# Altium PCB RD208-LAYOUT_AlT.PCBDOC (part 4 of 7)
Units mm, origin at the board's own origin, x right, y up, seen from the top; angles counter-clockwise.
Board outline 240 x 150 mm, 6 copper layers (TOP, Mid-Layer 1, Mid-Layer 2, Mid-Layer 3, Mid-Layer 4, BOTTOM), stack 1.422 mm thick; 773 components, 409 nets, 3936 pads, 97 vias.
Unrouted connection lines stored in the file: 1.
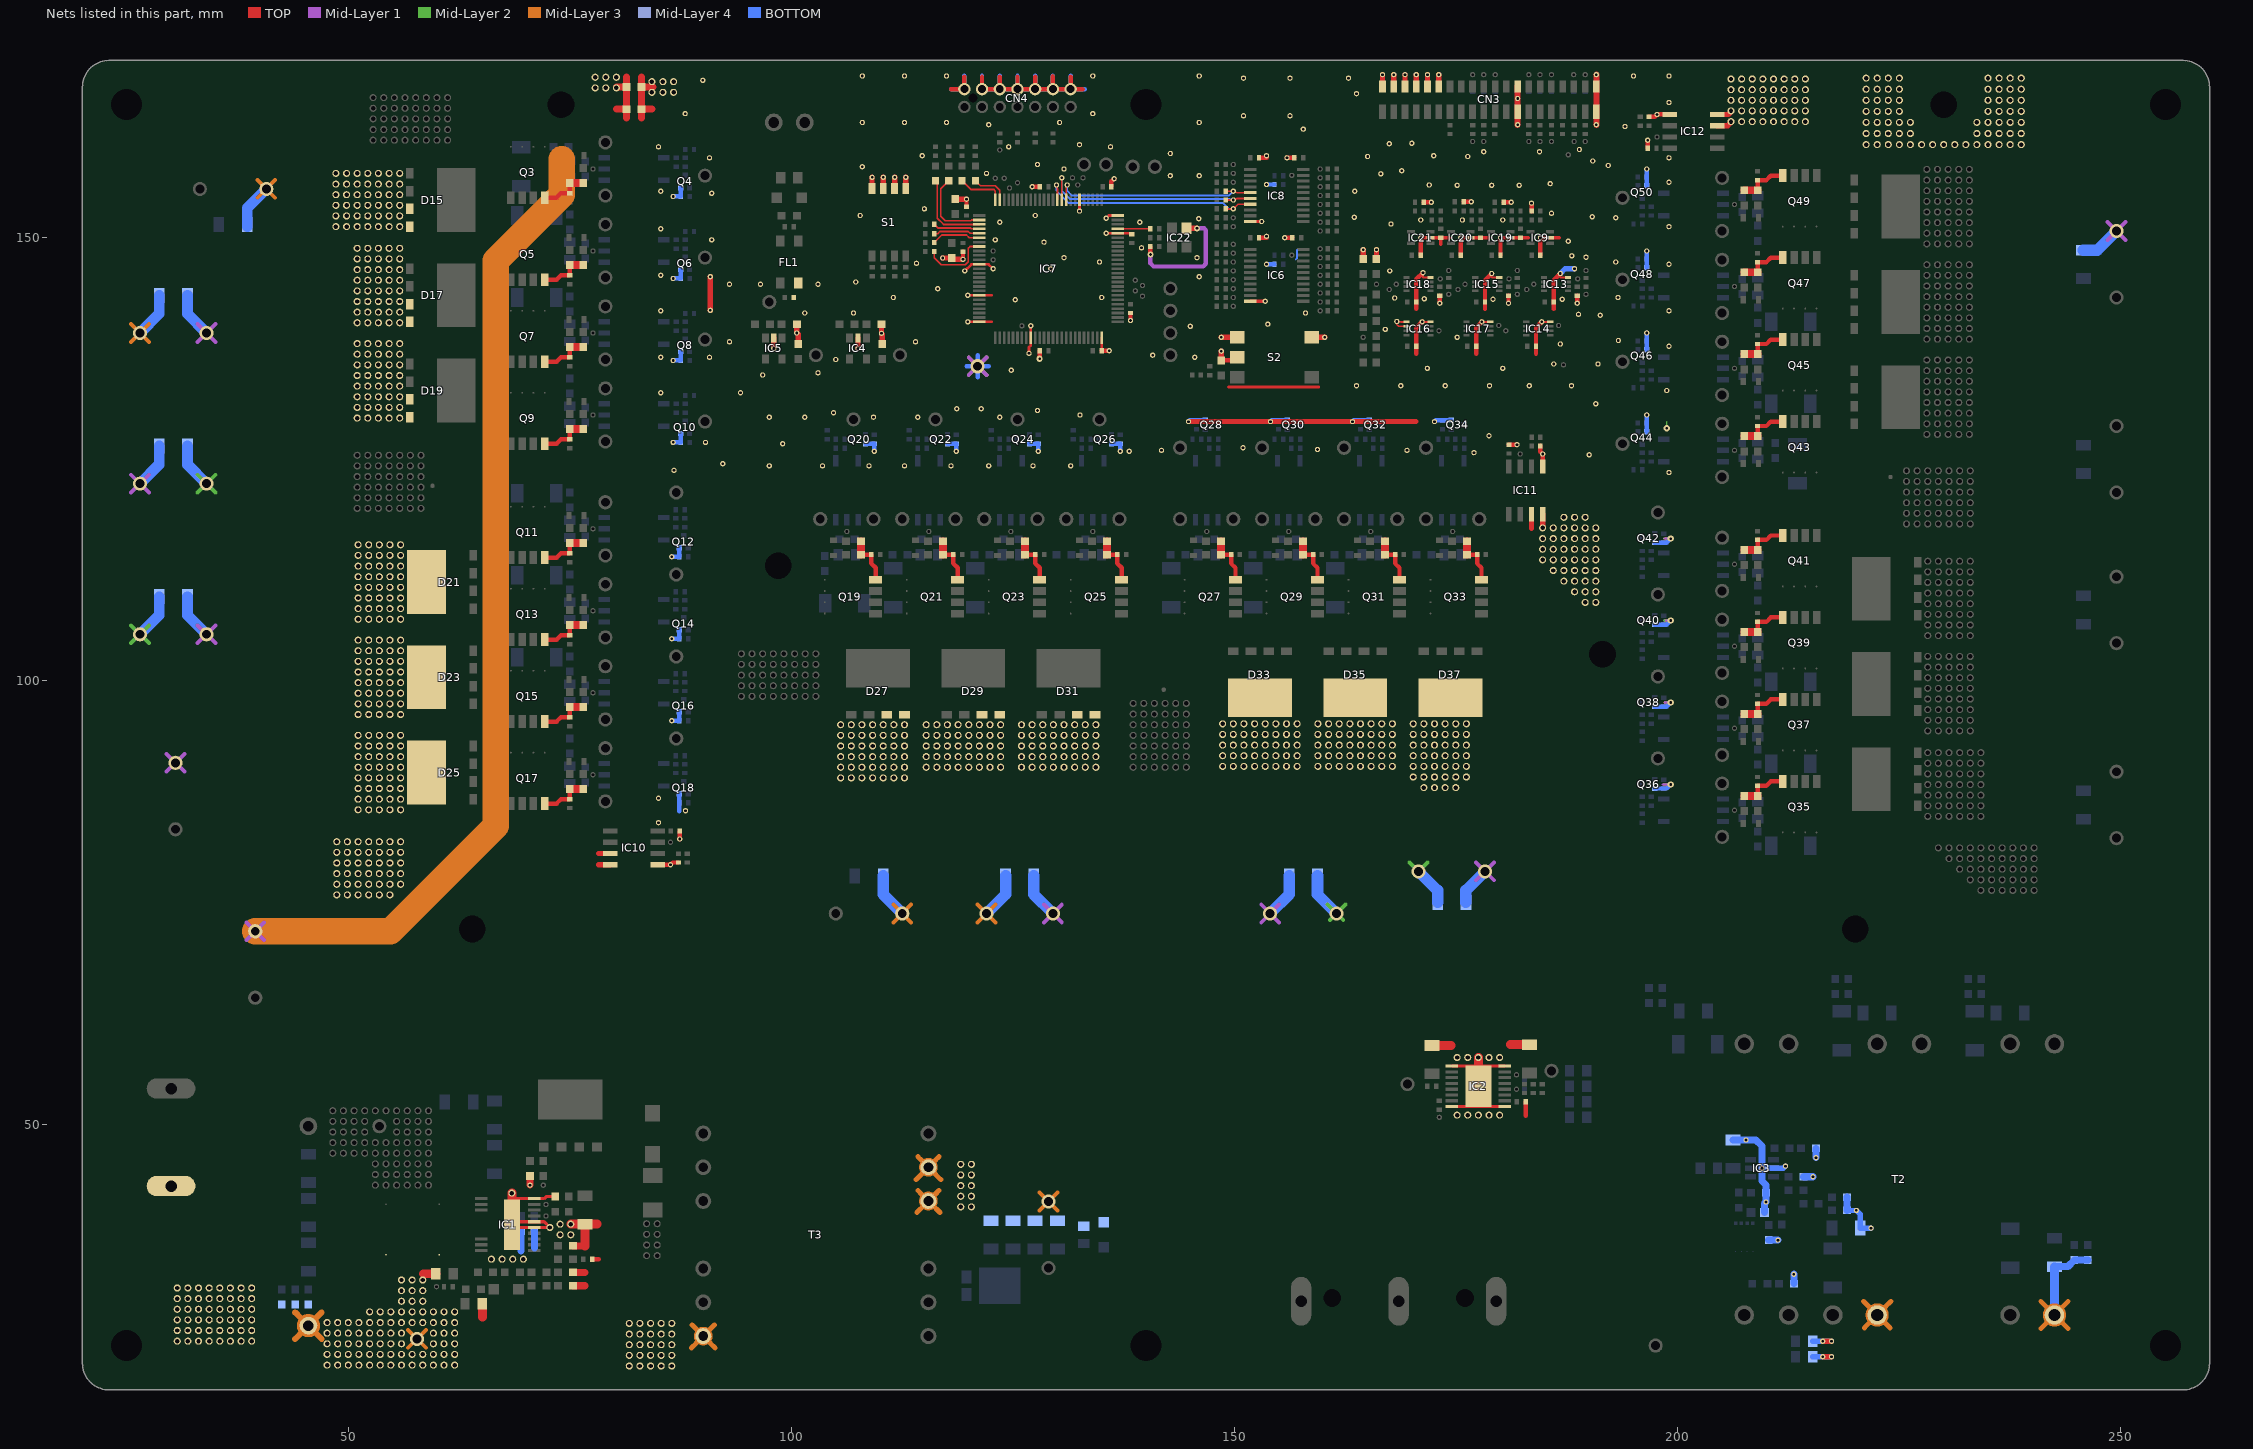
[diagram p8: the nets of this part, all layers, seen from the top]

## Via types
v1: diameter 0.7, hole 0.3, TOP to BOTTOM, 92 vias
v2: diameter 0.9, hole 0.5, TOP to BOTTOM, 4 vias
v3: diameter 1.6, hole 1, TOP to BOTTOM, 1 vias

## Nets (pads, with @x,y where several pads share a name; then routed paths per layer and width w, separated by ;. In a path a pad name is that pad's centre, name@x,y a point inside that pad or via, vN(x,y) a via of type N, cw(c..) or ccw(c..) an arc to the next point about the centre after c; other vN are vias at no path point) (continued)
CP_VL: IC7.34 IC8.5 pad.@131.1,155.95 pad.@149.85,155.25 R69.2 | length 24.3
  TOP w0.2: IC7.34@131,154.3 131,155.511 pad.@131.1,155.95 ; R69.2@149,155.25 pad.@149.85,155.25 150.265,155.075 IC8.5@151.75,155.075
  BOTTOM w0.2: pad.@131.1,155.95 131.1,155.3 131.65,154.75 149.35,154.75 pad.@149.85,155.25
CP_WH: IC7.35 IC8.6 pad.@130.5,156.75 pad.@149.85,154.25 R70.2 | length 26.4
  TOP w0.2: IC7.35@130.5,154.3 pad.@130.5,156.75 ; R70.2@149,154.25 pad.@149.85,154.25 150.265,154.425 IC8.6@151.75,154.425
  BOTTOM w0.2: pad.@130.5,156.75 130.5,155.3 131.45,154.35 149.411,154.35 pad.@149.85,154.25
CP_WL: IC7.36 IC8.7 pad.@129.9,155.95 pad.@149.85,153.25 R71.2 | length 26.1
  TOP w0.2: pad.@129.9,155.95 130,155.511 IC7.36@130,154.3 ; R71.2@149,153.25 pad.@149.85,153.25 150.375,153.775 IC8.7@151.75,153.775
  BOTTOM w0.2: pad.@129.9,155.95 129.9,155.3 131.3,153.9 148.7,153.9 149.35,153.25 pad.@149.85,153.25
CPLD_CLK: IC7.22 R79.2 | length 3.7
  TOP w0.2: IC7.22@136.8,151 R79.2@140.5,151
DBG_LED1: DS1.K IC7.49 | length 4.2
  TOP w0.2: DS1.K@120.75,156.425 121.325,155.85 123,155.85 123.5,155.35 IC7.49@123.5,154.3
DBG_LED2: DS2.K IC7.50 | length 5.2
  TOP w0.2: DS2.K@119.25,156.425 120.225,155.45 122.8,155.45 123,155.25 IC7.50@123,154.3
DBG_LED3: DS3.K IC7.52 | length 9
  TOP w0.2: DS3.K@117.75,156.425 116.85,155.525 116.85,152.4 117.35,151.9 120.25,151.9 120.35,152 IC7.52@121.2,152
DBG_LED4: DS4.K IC7.53 | length 9.3
  TOP w0.2: DS4.K@116.25,156.425 116.45,156.225 116.45,152.2 117.15,151.5 IC7.53@121.2,151.5
DBG_SW1: IC7.54 R210.2 | length 5.3
  TOP w0.2: R210.2@116.1,151.5 116.5,151.1 120.2,151.1 120.3,151 IC7.54@121.2,151
DBG_SW2: IC7.55 R211.2 | length 5.3
  TOP w0.2: R211.2@116.1,150.45 116.5,150.45 116.75,150.7 119.95,150.7 120.15,150.5 IC7.55@121.2,150.5
DBG_SW3: IC7.56 R212.2 | length 5.6
  TOP w0.2: R212.2@116.1,149.45 116.95,150.3 119.75,150.3 120.05,150 IC7.56@121.2,150
DBG_SW4: IC7.58 R213.2 | length 7.9
  TOP w0.2: R213.2@116.1,148.45 116.1,147.75 116.9,146.95 119.6,146.95 119.95,147.3 119.95,148.8 120.15,149 IC7.58@121.2,149
GD_U1: Q3.4 R176.2 R214.1 R245.2 | length 5.7
  TOP w0.5: Q3.4@72.155,154.5 73.5,154.5 74,155 R214.1@75,155 R245.2@75,156.15
  TOP w0.9: R245.2@75,156.15 R176.2@76.5,156.15
GD_U2: Q5.4 R177.2 R215.1 R246.2 | length 5.7
  TOP w0.5: Q5.4@72.155,145.25 73.5,145.25 74,145.75 R215.1@75,145.75 R246.2@75,146.9
  TOP w0.9: R246.2@75,146.9 R177.2@76.5,146.9
GD_U3: Q7.4 R178.2 R216.1 R247.2 | length 5.7
  TOP w0.5: Q7.4@72.155,136 73.5,136 74,136.5 R216.1@75,136.5 R247.2@75,137.65
  TOP w0.9: R247.2@75,137.65 R178.2@76.5,137.65
GD_U4: Q9.4 R179.2 R217.1 R249.2 | length 5.7
  TOP w0.5: Q9.4@72.155,126.75 73.5,126.75 74,127.25 R217.1@75,127.25 R249.2@75,128.4
  TOP w0.9: R249.2@75,128.4 R179.2@76.5,128.4
GD_U5: Q11.4 R180.2 R218.1 R251.2 | length 5.7
  TOP w0.5: Q11.4@72.155,113.9 73.5,113.9 74,114.4 R218.1@75,114.4 R251.2@75,115.55
  TOP w0.9: R251.2@75,115.55 R180.2@76.5,115.55
GD_U6: Q13.4 R181.2 R219.1 R253.2 | length 5.7
  TOP w0.5: Q13.4@72.155,104.65 73.5,104.65 74,105.15 R219.1@75,105.15 R253.2@75,106.3
  TOP w0.9: R253.2@75,106.3 R181.2@76.5,106.3
GD_U7: Q15.4 R182.2 R220.1 R255.2 | length 5.7
  TOP w0.5: Q15.4@72.155,95.4 73.5,95.4 74,95.9 R220.1@75,95.9 R255.2@75,97.05
  TOP w0.9: R255.2@75,97.05 R182.2@76.5,97.05
GD_U8: Q17.4 R183.2 R221.1 R257.2 | length 5.7
  TOP w0.5: Q17.4@72.155,86.15 73.5,86.15 74,86.65 R221.1@75,86.65 R257.2@75,87.8
  TOP w0.9: R257.2@75,87.8 R183.2@76.5,87.8
GD_V1: Q19.4 R168.2 R222.1 R258.2 | length 5.7
  TOP w0.5: R258.2@107.85,114.25 R222.1@109,114.25 109,113.25 109.5,112.75 Q19.4@109.5,111.405
  TOP w0.9: R258.2@107.85,114.25 R168.2@107.85,115.75
GD_V2: Q21.4 R169.2 R223.1 R260.2 | length 5.7
  TOP w0.5: R260.2@117.1,114.25 R223.1@118.25,114.25 118.25,113.25 118.75,112.75 Q21.4@118.75,111.405
  TOP w0.9: R260.2@117.1,114.25 R169.2@117.1,115.75
GD_V3: Q23.4 R170.2 R224.1 R262.2 | length 5.7
  TOP w0.5: R262.2@126.35,114.25 R224.1@127.5,114.25 127.5,113.25 128,112.75 Q23.4@128,111.405
  TOP w0.9: R262.2@126.35,114.25 R170.2@126.35,115.75
GD_V4: Q25.4 R171.2 R225.1 R266.2 | length 5.7
  TOP w0.5: R266.2@135.6,114.25 R225.1@136.75,114.25 136.75,113.25 137.25,112.75 Q25.4@137.25,111.405
  TOP w0.9: R266.2@135.6,114.25 R171.2@135.6,115.75
GD_V5: Q27.4 R172.2 R226.1 R264.2 | length 5.7
  TOP w0.5: R264.2@148.45,114.25 R226.1@149.6,114.25 149.6,113.25 150.1,112.75 Q27.4@150.1,111.405
  TOP w0.9: R264.2@148.45,114.25 R172.2@148.45,115.75
GD_V6: Q29.4 R173.2 R227.1 R268.2 | length 5.7
  TOP w0.5: R268.2@157.7,114.25 R227.1@158.85,114.25 158.85,113.25 159.35,112.75 Q29.4@159.35,111.405
  TOP w0.9: R268.2@157.7,114.25 R173.2@157.7,115.75
GD_V7: Q31.4 R174.2 R228.1 R270.2 | length 5.7
  TOP w0.5: R270.2@166.95,114.25 R228.1@168.1,114.25 168.1,113.25 168.6,112.75 Q31.4@168.6,111.405
  TOP w0.9: R270.2@166.95,114.25 R174.2@166.95,115.75
GD_V8: Q33.4 R175.2 R229.1 R272.2 | length 5.7
  TOP w0.5: R272.2@176.2,114.25 R229.1@177.35,114.25 177.35,113.25 177.85,112.75 Q33.4@177.85,111.405
  TOP w0.9: R272.2@176.2,114.25 R175.2@176.2,115.75
GD_W1: Q35.4 R184.2 R230.1 R274.2 | length 5.7
  TOP w0.5: R274.2@209,87 R230.1@209,88.15 210,88.15 210.5,88.65 Q35.4@211.845,88.65
  TOP w0.9: R184.2@207.5,87 R274.2@209,87
GD_W2: Q37.4 R185.2 R231.1 R276.2 | length 5.7
  TOP w0.5: R276.2@209,96.25 R231.1@209,97.4 210,97.4 210.5,97.9 Q37.4@211.845,97.9
  TOP w0.9: R185.2@207.5,96.25 R276.2@209,96.25
GD_W3: Q39.4 R186.2 R232.1 R278.2 | length 5.7
  TOP w0.5: R278.2@209,105.5 R232.1@209,106.65 210,106.65 210.5,107.15 Q39.4@211.845,107.15
  TOP w0.9: R186.2@207.5,105.5 R278.2@209,105.5
GD_W4: Q41.4 R187.2 R233.1 R280.2 | length 5.7
  TOP w0.5: R280.2@209,114.75 R233.1@209,115.9 210,115.9 210.5,116.4 Q41.4@211.845,116.4
  TOP w0.9: R187.2@207.5,114.75 R280.2@209,114.75
GD_W5: Q43.4 R188.2 R234.1 R282.2 | length 5.7
  TOP w0.5: R282.2@209,127.6 R234.1@209,128.75 210,128.75 210.5,129.25 Q43.4@211.845,129.25
  TOP w0.9: R188.2@207.5,127.6 R282.2@209,127.6
GD_W6: Q45.4 R189.2 R235.1 R284.2 | length 5.7
  TOP w0.5: R284.2@209,136.85 R235.1@209,138 210,138 210.5,138.5 Q45.4@211.845,138.5
  TOP w0.9: R189.2@207.5,136.85 R284.2@209,136.85
GD_W7: Q47.4 R190.2 R236.1 R286.2 | length 5.7
  TOP w0.5: R286.2@209,146.1 R236.1@209,147.25 210,147.25 210.5,147.75 Q47.4@211.845,147.75
  TOP w0.9: R190.2@207.5,146.1 R286.2@209,146.1
GD_W8: Q49.4 R191.2 R237.1 R288.2 | length 5.7
  TOP w0.5: R288.2@209,155.35 R237.1@209,156.5 210,156.5 210.5,157 Q49.4@211.845,157
  TOP w0.9: R191.2@207.5,155.35 R288.2@209,155.35
GND: C1.2 C2.2 C3.2 C4.2 C6.2 C7.2 C8.1 C9.2 C10.2 C11.2 C12.2 C13.2 C14.2 C15.2 C16.2 C20.2 C21.2 C56.2 C66.2 C67.2 C71.2 C84.2 C103.2 C129.2 C130.2 C131.2 C132.2 C137.2 C138.2 CN1.2 D3.A IC1.15 IC1.16 IC1.20 IC1.21 IC2.1 IC2.8 IC2.9 IC2.16 IC2.17 IC3.2 IC10.3 IC10.4 IC11.3 IC11.4 IC12.3 IC12.4 pad.@30.7,25.5 pad.@30.7,26.7 pad.@30.7,27.9 pad.@30.7,29.1 pad.@30.7,30.3 pad.@30.7,31.5 pad.@31.9,25.5 pad.@31.9,26.7 pad.@31.9,27.9 pad.@31.9,29.1 pad.@31.9,30.3 pad.@31.9,31.5 pad.@33.1,25.5 pad.@33.1,26.7 pad.@33.1,27.9 pad.@33.1,29.1 pad.@33.1,30.3 pad.@33.1,31.5 pad.@34.3,25.5 pad.@34.3,26.7 pad.@34.3,27.9 pad.@34.3,29.1 pad.@34.3,30.3 pad.@34.3,31.5 pad.@35.5,25.5 pad.@35.5,26.7 pad.@35.5,27.9 pad.@35.5,29.1 pad.@35.5,30.3 pad.@35.5,31.5 pad.@36.7,25.5 pad.@36.7,26.7 pad.@36.7,27.9 pad.@36.7,29.1 pad.@36.7,30.3 pad.@36.7,31.5 pad.@37.9,25.5 pad.@37.9,26.7 pad.@37.9,27.9 pad.@37.9,29.1 pad.@37.9,30.3 pad.@37.9,31.5 pad.@39.1,25.5 pad.@39.1,26.7 pad.@39.1,27.9 pad.@39.1,29.1 pad.@39.1,30.3 pad.@39.1,31.5 pad.@47.6,22.8 pad.@47.6,24 pad.@47.6,25.2 pad.@47.6,26.4 pad.@47.6,27.6 pad.@48.7,75.85 pad.@48.7,77.05 pad.@48.7,78.25 pad.@48.7,79.45 pad.@48.7,80.65 pad.@48.7,81.85 pad.@48.8,22.8 pad.@48.8,24 pad.@48.8,25.2 pad.@48.8,26.4 pad.@48.8,27.6 pad.@49.9,75.85 pad.@49.9,77.05 pad.@49.9,78.25 pad.@49.9,79.45 pad.@49.9,80.65 pad.@49.9,81.85 pad.@50,22.8 pad.@50,24 pad.@50,25.2 pad.@50,26.4 pad.@50,27.6 pad.@51.1,75.85 pad.@51.1,77.05 pad.@51.1,78.25 pad.@51.1,79.45 pad.@51.1,80.65 pad.@51.1,81.85 pad.@51.2,22.8 pad.@51.2,24 pad.@51.2,25.2 pad.@51.2,26.4 pad.@51.2,27.6 pad.@52.3,75.85 pad.@52.3,77.05 pad.@52.3,78.25 pad.@52.3,79.45 pad.@52.3,80.65 pad.@52.3,81.85 pad.@52.4,22.8 pad.@52.4,24 pad.@52.4,25.2 pad.@52.4,26.4 pad.@52.4,27.6 pad.@52.4,28.8 pad.@53.5,75.85 pad.@53.5,77.05 pad.@53.5,78.25 pad.@53.5,79.45 pad.@53.5,80.65 pad.@53.5,81.85 pad.@53.6,22.8 pad.@53.6,24 pad.@53.6,25.2 pad.@53.6,26.4 pad.@53.6,27.6 pad.@53.6,28.8 pad.@54.7,75.85 pad.@54.7,77.05 pad.@54.7,78.25 pad.@54.7,79.45 pad.@54.7,80.65 pad.@54.7,81.85 pad.@54.8,22.8 pad.@54.8,24 pad.@54.8,25.2 pad.@54.8,26.4 pad.@54.8,27.6 pad.@54.8,28.8 pad.@55.9,77.05 pad.@55.9,78.25 pad.@55.9,79.45 pad.@55.9,80.65 pad.@55.9,81.85 pad.@56,22.8 pad.@56,24 pad.@56,25.2 pad.@56,26.4 pad.@56,27.6 pad.@56,28.8 pad.@56,30 pad.@56,31.2 pad.@56,32.4 pad.@57.2,22.8 pad.@57.2,24 pad.@57.2,27.6 pad.@57.2,28.8 pad.@57.2,30 pad.@57.2,31.2 pad.@57.2,32.4 pad.@58.4,22.8 pad.@58.4,24 pad.@58.4,27.6 pad.@58.4,28.8 pad.@58.4,30 pad.@58.4,31.2 pad.@58.4,32.4 pad.@59.6,22.8 pad.@59.6,24 pad.@59.6,25.2 pad.@59.6,26.4 pad.@59.6,27.6 pad.@59.6,28.8 pad.@60.8,22.8 pad.@60.8,24 pad.@60.8,25.2 pad.@60.8,26.4 pad.@60.8,27.6 pad.@60.8,28.8 pad.@62,22.8 pad.@62,24 pad.@62,25.2 pad.@62,26.4 pad.@62,27.6 pad.@62,28.8 pad.@66.15,34.75 pad.@67.35,34.75 pad.@68.45,42.2 pad.@68.55,34.75 pad.@69.75,34.75 pad.@70.5,43.1 pad.@72.75,38.325 pad.@73.9,37.5 pad.@73.9,38.7 pad.@75.1,37.5 pad.@75.1,38.7 pad.@77.85,166.9 pad.@77.85,168.1 pad.@79.05,166.9 pad.@79.05,168.1 pad.@80.25,166.9 pad.@80.25,168.1 pad.@81.7,22.7 pad.@81.7,23.9 pad.@81.7,25.1 pad.@81.7,26.3 pad.@81.7,27.5 pad.@82.9,22.7 pad.@82.9,23.9 pad.@82.9,25.1 pad.@82.9,26.3 pad.@82.9,27.5 pad.@84.1,22.7 pad.@84.1,23.9 pad.@84.1,25.1 pad.@84.1,26.3 pad.@84.1,27.5 pad.@85.3,22.7 pad.@85.3,23.9 pad.@85.3,25.1 pad.@85.3,26.3 pad.@85.3,27.5 pad.@86.5,22.7 pad.@86.5,23.9 pad.@86.5,25.1 pad.@86.5,26.3 pad.@86.5,27.5 pad.@119.1,40.65 pad.@119.1,41.85 pad.@119.1,43.05 pad.@119.1,44.25 pad.@119.1,45.45 pad.@120.3,40.65 pad.@120.3,41.85 pad.@120.3,43.05 pad.@120.3,44.25 pad.@120.3,45.45 pad.@175.1,51 pad.@175.1,57.5 pad.@176.3,51 pad.@176.3,57.5 pad.@177.5,51 pad.@177.5,57.5 pad.@178.7,51 pad.@178.7,57.5 pad.@179.9,51 pad.@179.9,57.5 pad.@184.75,113.65 pad.@184.75,114.85 pad.@184.75,116.05 pad.@184.75,117.25 pad.@185.95,112.45 pad.@185.95,113.65 pad.@185.95,114.85 pad.@185.95,116.05 pad.@185.95,117.25 pad.@187.15,111.25 pad.@187.15,112.45 pad.@187.15,113.65 pad.@187.15,114.85 pad.@187.15,116.05 pad.@187.15,117.25 pad.@187.15,118.45 pad.@188.35,110.05 pad.@188.35,111.25 pad.@188.35,112.45 pad.@188.35,113.65 pad.@188.35,114.85 pad.@188.35,116.05 pad.@188.35,117.25 pad.@188.35,118.45 pad.@189.55,108.85 pad.@189.55,110.05 pad.@189.55,111.25 pad.@189.55,112.45 pad.@189.55,113.65 pad.@189.55,114.85 pad.@189.55,116.05 pad.@189.55,117.25 pad.@189.55,118.45 pad.@190.75,108.85 pad.@190.75,110.05 pad.@190.75,111.25 pad.@190.75,112.45 pad.@190.75,113.65 pad.@190.75,114.85 pad.@190.75,116.05 pad.@190.75,117.25 pad.@206,163.1 pad.@206,164.3 pad.@206,165.5 pad.@206,166.7 pad.@206,167.9 pad.@207.2,163.1 pad.@207.2,164.3 pad.@207.2,165.5 pad.@207.2,166.7 pad.@207.2,167.9 pad.@207.7,48.2 pad.@208.4,163.1 pad.@208.4,164.3 pad.@208.4,165.5 pad.@208.4,166.7 pad.@208.4,167.9 pad.@209.5,45 pad.@209.6,163.1 pad.@209.6,164.3 pad.@209.6,165.5 pad.@209.6,166.7 pad.@209.6,167.9 pad.@209.95,41.2 pad.@210.8,163.1 pad.@210.8,164.3 pad.@210.8,165.5 pad.@210.8,166.7 pad.@210.8,167.9 pad.@211.3,36.9 pad.@212,163.1 pad.@212,164.3 pad.@212,165.5 pad.@212,166.7 pad.@212,167.9 pad.@212.15,45.25 pad.@213.1,33.05 pad.@213.2,163.1 pad.@213.2,164.3 pad.@213.2,165.5 pad.@213.2,166.7 pad.@213.2,167.9 pad.@214.4,163.1 pad.@214.4,164.3 pad.@214.4,165.5 pad.@214.4,166.7 pad.@214.4,167.9 pad.@215.6,46.2 pad.@215.25,44.05 pad.@216.35,23.75 pad.@216.35,25.5 pad.@217.35,23.75 pad.@217.35,25.5 pad.@220.15,40.25 pad.@221.8,38.25 pad.@221.25,160.5 pad.@221.25,161.75 pad.@221.25,163 pad.@221.25,164.25 pad.@221.25,165.5 pad.@221.25,166.75 pad.@221.25,168 pad.@222.5,160.5 pad.@222.5,161.75 pad.@222.5,163 pad.@222.5,164.25 pad.@222.5,165.5 pad.@222.5,166.75 pad.@222.5,168 pad.@223.75,160.5 pad.@223.75,161.75 pad.@223.75,163 pad.@223.75,164.25 pad.@223.75,165.5 pad.@223.75,166.75 pad.@223.75,168 pad.@225,160.5 pad.@225,161.75 pad.@225,163 pad.@225,164.25 pad.@225,165.5 pad.@225,166.75 pad.@225,168 pad.@226.25,160.5 pad.@226.25,161.75 pad.@226.25,163 pad.@227.5,160.5 pad.@228.75,160.5 pad.@230,160.5 pad.@231.25,160.5 pad.@232.5,160.5 pad.@233.75,160.5 pad.@233.75,161.75 pad.@233.75,163 pad.@235,160.5 pad.@235,161.75 pad.@235,163 pad.@235,164.25 pad.@235,165.5 pad.@235,166.75 pad.@235,168 pad.@236.25,160.5 pad.@236.25,161.75 pad.@236.25,163 pad.@236.25,164.25 pad.@236.25,165.5 pad.@236.25,166.75 pad.@236.25,168 pad.@237.5,160.5 pad.@237.5,161.75 pad.@237.5,163 pad.@237.5,164.25 pad.@237.5,165.5 pad.@237.5,166.75 pad.@237.5,168 pad.@238.75,160.5 pad.@238.75,161.75 pad.@238.75,163 pad.@238.75,164.25 pad.@238.75,165.5 pad.@238.75,166.75 pad.@238.75,168 R8.1 R11.1 R13.2 R15.2 R16.1 R19.2 R26.2 R31.2 R32.2 R33.2 R34.2 R196.2 R197.2 R202.2 R206.2 R207.2 R208.2 R298.2 R299.2 R300.2 R307.2 R308.2 T2.4 T2.8 T3.6 T3.10 T3.11 TP2.1 | length 348.5
  TOP w0.35: C13.2@73.35,41.8 72.325,41.8 72.1,41.575 IC1.20@70.988,41.575 68.47,41.575 IC1.21@68.47,38.65 ; IC2.16@174.513,51.975 IC2.1@180.488,51.975 ; IC2.9@174.513,56.525 177.5,56.525 IC2.8@180.488,56.525 ; IC1.21@68.47,38.65 68.795,38.975 IC1.16@70.988,38.975 72.1,38.975 pad.@72.75,38.325 IC1.15@70.988,38.325 68.795,38.325 IC1.21@68.47,38.65
  TOP w0.5: C12.2@77.5,34.75 78.25,34.75 ; 182.85,50.95 R26.2@182.85,52.5
  TOP w0.6: 78.25,79.245 IC10.4@79.567,79.245 ; 78.25,80.515 IC10.3@79.567,80.515 ; 183.485,117.2 IC11.3@183.485,118.817 ; IC11.4@184.755,118.817 184.755,117.345 pad.@184.85,117.25 ; IC12.3@204.432,162.635 205.635,162.635 pad.@206,163 ; IC12.4@204.432,163.905 205.705,163.905 pad.@206,164.2 ; pad.@216.35,23.75 pad.@217.35,23.75 ; pad.@216.35,25.5 pad.@217.35,25.5
  TOP w0.8: pad.@70.5,43.1 R207.2@70.5,44.15 ; R13.2@75.35,31.75 76.7,31.75 ; C10.2@75.35,33.25 76.7,33.25 ; R16.1@75.35,36.25 76.7,36.25 ; 80.25,164.5 R299.2@81.4,164.5 ; pad.@80.25,167 R298.2@81.4,167 ; 81.4,163.5 R299.2@81.4,164.5 ; 81.4,168.15 R298.2@81.4,167 ; R299.2@81.4,164.5 R298.2@81.4,167
  TOP w1: 58.5,33.1 C14.2@59.875,33.1 ; 65.125,28.2 C4.2@65.125,29.7 ; IC1.21@68.45,39.85 pad.@68.45,42.2 ; pad.@75.1,38.7 R19.2@76.7,38.7 ; 76.7,36.25 R19.2@76.7,38.7 ; 78.05,38.7 R19.2@76.7,38.7 ; C15.2@172.25,58.85 174.4,58.85 ; IC2.17@177.5,54.25 177.5,56.525 pad.@177.5,57.5 ; 181.1,58.95 C16.2@183.25,58.95
  Mid-Layer 1 w0.44: 29.5,89.75 C67.2@30.5,90.75 ; 29.5,91.75 C67.2@30.5,90.75 ; 31.5,89.75 C67.2@30.5,90.75 ; 31.5,91.75 C67.2@30.5,90.75 ; 33,104.25 C56.2@34,105.25 ; 33,106.25 C56.2@34,105.25 ; 35,104.25 C56.2@34,105.25 ; 35,106.25 C56.2@34,105.25 ; 38.5,70.75 C66.2@39.5,71.75 ; 38.5,72.75 C66.2@39.5,71.75 ; 40.5,70.75 C66.2@39.5,71.75 ; 40.5,72.75 C66.2@39.5,71.75 ; 177.25,77.5 C71.2@178.25,78.5 ; 177.25,79.5 C71.2@178.25,78.5 ; 179.25,77.5 C71.2@178.25,78.5 ; 179.25,79.5 C71.2@178.25,78.5 ; 248.5,149.75 C84.2@249.5,150.75 ; 248.5,151.75 C84.2@249.5,150.75 ; 250.5,149.75 C84.2@249.5,150.75 ; 250.5,151.75 C84.2@249.5,150.75
  Mid-Layer 3 w0.44: 56.75,24.75 TP2.1@57.75,25.75 ; 56.75,26.75 TP2.1@57.75,25.75 ; 58.75,24.75 TP2.1@57.75,25.75 ; 58.75,26.75 TP2.1@57.75,25.75 ; 128,40.25 C7.2@129,41.25 ; 128,42.25 C7.2@129,41.25 ; 130,40.25 C7.2@129,41.25 ; 130,42.25 C7.2@129,41.25
  Mid-Layer 3 w0.56: 88.7,24.72 89.308,25.328 89.679,25.699 T3.6@90.05,26.07 ; 88.8,27.32 89.679,26.441 T3.6@90.05,26.07 ; 91.3,27.32 90.421,26.441 T3.6@90.05,26.07 ; 91.4,24.72 90.792,25.328 90.421,25.699 T3.6@90.05,26.07 ; 114.05,43.72 114.672,44.342 115.079,44.749 T3.11@115.45,45.12 ; 114.15,40.01 115.079,40.939 T3.10@115.45,41.31 ; 114.25,42.51 114.708,42.052 115.079,41.681 T3.10@115.45,41.31 ; 114.25,46.32 114.672,45.898 115.079,45.491 T3.11@115.45,45.12 ; 116.65,42.51 116.192,42.052 115.821,41.681 T3.10@115.45,41.31 ; 116.65,46.32 116.228,45.898 115.821,45.491 T3.11@115.45,45.12 ; 116.75,40.01 115.821,40.939 T3.10@115.45,41.31 ; 116.85,43.72 116.228,44.342 115.821,44.749 T3.11@115.45,45.12 ; 220.95,30 221.58,29.37 222.04,28.91 T2.4@222.5,28.45 ; 221.05,27 222.04,27.99 T2.4@222.5,28.45 ; 223.95,27 222.96,27.99 T2.4@222.5,28.45 ; 224.05,30 223.42,29.37 222.96,28.91 T2.4@222.5,28.45 ; 240.95,30 241.616,29.334 242.04,28.91 T2.8@242.5,28.45 ; 241,26.95 242.04,27.99 T2.8@242.5,28.45 ; 244,26.95 242.96,27.99 T2.8@242.5,28.45 ; 244.05,30 243.384,29.334 242.96,28.91 T2.8@242.5,28.45
  Mid-Layer 3 w0.66: 44,25.75 45.04,26.79 C1.2@45.5,27.25 ; 44,28.75 44.615,28.135 45.04,27.71 C1.2@45.5,27.25 ; 47,25.75 45.96,26.79 C1.2@45.5,27.25 ; 47,28.75 46.385,28.135 45.96,27.71 C1.2@45.5,27.25
  Mid-Layer 3 w1.05: 89.679,25.699 ccw(c90.05,26.07) 90.421,25.699 ccw(c90.05,26.07) 90.575,26.07 ccw(c90.05,26.07) 90.421,26.441 ccw(c90.05,26.07) 89.679,26.441 ccw(c90.05,26.07) 89.679,25.699 ; 115.079,40.939 cw(c115.45,41.31) 115.079,41.681 cw(c115.45,41.31) 115.821,41.681 cw(c115.45,41.31) 115.975,41.31 cw(c115.45,41.31) 115.821,40.939 cw(c115.45,41.31) 115.079,40.939 ; 115.079,44.749 cw(c115.45,45.12) 115.079,45.491 cw(c115.45,45.12) 115.821,45.491 cw(c115.45,45.12) 115.975,45.12 cw(c115.45,45.12) 115.821,44.749 cw(c115.45,45.12) 115.079,44.749
  Mid-Layer 3 w1.3: 45.04,26.79 cw(c45.5,27.25) 45.04,27.71 cw(c45.5,27.25) 45.96,27.71 cw(c45.5,27.25) 46.15,27.25 cw(c45.5,27.25) 45.96,26.79 cw(c45.5,27.25) 45.04,26.79 ; 222.04,27.99 cw(c222.5,28.45) 222.04,28.91 cw(c222.5,28.45) 222.96,28.91 cw(c222.5,28.45) 223.15,28.45 cw(c222.5,28.45) 222.96,27.99 cw(c222.5,28.45) 222.04,27.99 ; 242.04,27.99 cw(c242.5,28.45) 242.04,28.91 cw(c242.5,28.45) 242.96,28.91 cw(c242.5,28.45) 243.15,28.45 cw(c242.5,28.45) 242.96,27.99 cw(c242.5,28.45) 242.04,27.99
  Mid-Layer 3 w3: C66.2@39.5,71.75 54.75,71.75 66.65,83.65 66.65,147.4 74.1,154.85 74.1,158.85
  BOTTOM w0.6: pad.@209.5,45 IC3.2@210.81,45 211.9,45 pad.@212.15,45.25 ; C137.2@215.225,23.75 pad.@216.35,23.75 pad.@217.35,23.75 ; C138.2@215.225,25.5 pad.@216.35,25.5 pad.@217.35,25.5 ; R31.2@219.1,40.25 pad.@220.15,40.25 220.6,39.8 C21.2@220.6,38.25 pad.@221.8,38.25
  BOTTOM w0.8: 69.5,35.7 R11.1@69.5,37.9 ; 71,36 C8.1@71,37.9 ; C129.2@206.25,48.2 pad.@207.7,48.2 208.8,48.2 209.5,47.5 pad.@209.5,45 209.5,43.55 209.95,43.1 C103.2@209.95,42.25 pad.@209.95,41.2 209.76,41.01 R33.2@209.76,40 ; R208.2@210.25,36.9 pad.@211.3,36.9 ; R197.2@213.1,32 pad.@213.1,33.05 ; R34.2@214.2,44.05 pad.@215.25,44.05 ; pad.@215.6,46.2 R32.2@215.6,47.25 ; R31.2@219.1,40.25 R300.2@219.1,41.75 ; C20.2@242.5,33.9 244,33.9 R307.2@244.75,34.65 R308.2@246.25,34.65
  BOTTOM w1: T2.8@242.5,28.45 C20.2@242.5,33.9
  BOTTOM w1.2: R196.2@31.85,109.5 31.85,107.4 C56.2@34,105.25
  BOTTOM w1.3: R202.2@176.1,75 176.1,76.35 C71.2@178.25,78.5 ; R206.2@245.75,148.6 247.35,148.6 C84.2@249.5,150.75
GND_D: C25.2 C27.2 C28.2 C29.2 C30.2 C31.2 C32.2 C33.2 C34.2 C35.2 C36.2 C37.2 C38.2 C39.2 C40.2 C41.2 C42.2 C43.2 C44.2 C45.2 C46.2 C61.2 C75.2 C89.2 C90.2 C91.2 C92.2 C93.2 C94.2 C95.2 C97.2 C99.2 C101.2 C102.2 C133.2 C134.2 C135.2 C136.2 C139.2 C140.2 C141.2 CN3.1 CN3.2 CN3.15 CN3.16 CN3.29 CN3.31 CN3.33 CN3.35 CN3.37 CN3.39 CN4.1 CN4.3 CN4.5 CN4.7 CN4.9 CN4.11 CN4.13 FL1.4 IC4.2 IC5.2 IC6.10 IC7.21 IC7.25 IC7.31 IC7.62 IC7.69 IC7.75 IC7.84 IC7.100 IC8.10 IC9.2 IC10.5 IC11.5 IC12.5 IC13.4 IC14.4 IC15.4 IC16.4 IC16.5 IC16.6 IC17.4 IC18.4 IC19.2 IC20.2 IC21.2 IC22.2 pad.@84.25,166.4 pad.@84.25,167.6 pad.@85,84 pad.@85,86.75 pad.@85,160.25 pad.@85.5,166.4 pad.@85.5,167.6 pad.@85.25,132.5 pad.@85.25,136.5 pad.@85.25,141.75 pad.@85.25,145.75 pad.@85.25,151 pad.@85.25,155.25 pad.@86.5,95.5 pad.@86.5,104.75 pad.@86.5,114 pad.@86.7,166.4 pad.@86.7,167.6 pad.@86.35,79.245 pad.@86.65,126.9 pad.@86.65,136.15 pad.@86.65,145.4 pad.@86.65,154.65 pad.@86.75,123.75 pad.@87.4,82.15 pad.@88,164 pad.@88.05,85.35 pad.@90,167.75 pad.@90.3,126.9 pad.@90.75,136.5 pad.@90.75,159 pad.@90.85,141.8 pad.@90.85,145.6 pad.@91,149.75 pad.@91,155 pad.@92.25,124.5 pad.@93,138.25 pad.@93,144.75 pad.@94.25,132.5 pad.@96.5,144.75 pad.@96.75,134.5 pad.@97.5,124.25 pad.@97.5,129.75 pad.@98,137.5 pad.@99,126.75 pad.@100.6,139.25 pad.@101.5,129.75 pad.@101.5,141.5 pad.@103,134.75 pad.@103,144.75 pad.@103.5,124.25 pad.@104.75,130.25 pad.@105,136.25 pad.@107,141.5 pad.@107.5,137.5 pad.@107.25,145 pad.@107.75,152.5 pad.@108,158 pad.@108,163 pad.@108,168.25 pad.@108.75,124.25 pad.@109.25,129.75 pad.@109.35,125.9 pad.@109.095,156.8 pad.@110.15,139.2 pad.@110.365,156.8 pad.@111.5,143.25 pad.@111.635,156.8 pad.@112.75,124.25 pad.@112.75,163 pad.@112.75,168.25 pad.@112.905,156.8 pad.@114,138.25 pad.@114.1,147.1 pad.@114.25,129.75 pad.@114.75,159.25 pad.@115,153.25 pad.@116.5,144.25 pad.@117.05,147.7 pad.@117.5,163 pad.@117.5,168.25 pad.@118,124.25 pad.@118.6,125.9 pad.@118.65,130.7 pad.@119.9,140.5 pad.@119.9,143.5 pad.@119.35,147.55 pad.@119.55,146.25 pad.@119.75,154.35 pad.@121.4,130.7 pad.@122,157.25 pad.@122.25,124.25 pad.@122.25,162.75 pad.@122.75,146.5 pad.@123,149.75 pad.@123.5,129.75 pad.@123.5,151.75 pad.@124.5,160.25 pad.@124.8,135.05 pad.@125.25,143 pad.@126.8,136.95 pad.@127,140.05 pad.@127.5,152.5 pad.@127.15,155.75 pad.@127.25,124.25 pad.@127.75,130.5 pad.@127.75,158.25 pad.@127.85,125.9 pad.@128.5,149.5 pad.@129.25,146.5 pad.@130.25,163 pad.@130.75,147.75 pad.@130.75,157.75 pad.@131.5,124.25 pad.@132.5,153 pad.@132.5,160.5 pad.@132.55,130 pad.@134,164 pad.@134,168.25 pad.@134.75,147.25 pad.@135,143.25 pad.@135.5,150.5 pad.@135.5,152.2 pad.@135.85,137.25 pad.@136,160.25 pad.@136.4,156.65 pad.@137.1,125.9 pad.@138.1,125.9 pad.@138.25,140.65 pad.@139.3,151.75 pad.@139.5,148.85 pad.@140.75,136.75 pad.@141.75,126 pad.@142.75,157 pad.@142.75,159.5 pad.@144.8,129.25 pad.@145,140 pad.@145.5,136.5 pad.@145.75,147.75 pad.@145.95,152.15 pad.@146,145.6 pad.@146,157 pad.@146,163 pad.@146,168.25 pad.@148.5,137.2 pad.@148.5,138.75 pad.@150.95,126.3 pad.@151,163.75 pad.@151,168 pad.@153.05,151.825 pad.@153.6,147 pad.@153.6,150.15 pad.@153.6,156 pad.@153.6,159.25 pad.@153.45,142.825 pad.@153.75,140.25 pad.@154.05,129.25 pad.@155.9,159 pad.@155.65,150 pad.@156.25,163.75 pad.@156.25,168 pad.@157.75,162.25 pad.@158,141.5 pad.@159.35,126.1 pad.@160.15,138.75 pad.@162.85,168 pad.@163.3,129.25 pad.@163.5,152.3 pad.@163.55,155.25 pad.@163.75,133.3 pad.@163.75,166.25 pad.@164.5,148.65 pad.@165,159.15 pad.@166,148.65 pad.@166.5,157.2 pad.@166.685,168.4 pad.@167,139.65 pad.@167.5,146.25 pad.@167.45,160.6 pad.@167.65,151.55 pad.@167.955,168.4 pad.@168.3,140.55 pad.@168.05,143.2 pad.@168.75,133.3 pad.@168.85,157.55 pad.@169.45,126 pad.@169.225,168.4 pad.@170,160.65 pad.@170.495,168.4 pad.@171,150 pad.@171,152 pad.@171.4,143.1 pad.@171.15,140.5 pad.@171.25,146.05 pad.@171.75,135.25 pad.@171.95,155.95 pad.@171.765,168.4 pad.@172.2,154 pad.@172.45,159.25 pad.@172.55,129.25 pad.@173.15,142.6 pad.@173.035,168.4 pad.@173.75,133.3 pad.@175.1,138.75 pad.@175.1,155.9 pad.@175.5,150 pad.@175.7,152 pad.@176.3,159.15 pad.@176.7,154.05 pad.@177,125.75 pad.@177.9,140.5 pad.@178.1,159.7 pad.@178.7,127.65 pad.@178.75,133.3 pad.@179,145.95 pad.@179,155.9 pad.@179.15,143.05 pad.@180,150 pad.@180.9,142.6 pad.@180.25,135.25 pad.@180.25,152 pad.@181.2,154 pad.@181.85,126.65 pad.@181.925,162.75 pad.@181.925,165.7 pad.@182.1,155.9 pad.@183.5,153.9 pad.@183.25,133.3 pad.@184.4,159.7 pad.@184.5,150 pad.@184.65,140.5 pad.@184.755,125.6 pad.@185.6,156.1 pad.@185.75,152.75 pad.@186,135.75 pad.@186.75,138 pad.@186.75,145.95 pad.@186.95,143.05 pad.@187.65,149.6 pad.@188,133.3 pad.@188.05,147.95 pad.@188.8,141.35 pad.@188.9,159.95 pad.@188.35,146.5 pad.@188.65,142.6 pad.@189.65,147.8 pad.@190,125.5 pad.@190.4,158.65 pad.@190.35,152.35 pad.@190.75,131.25 pad.@190.815,162.75 pad.@190.815,168.4 pad.@191,135.75 pad.@191.25,141.25 pad.@192.15,158.15 pad.@193,147.25 pad.@193,152.25 pad.@193.3,138.4 pad.@193.25,143.25 pad.@194.05,162.55 pad.@195,168.25 pad.@196.5,130 pad.@196.5,139.25 pad.@196.5,148.5 pad.@196.5,157.75 pad.@196.6,161 pad.@197.65,163.905 pad.@198.75,132.75 pad.@199,123.5 pad.@199,137.75 pad.@199,141.75 pad.@199,147 pad.@199,151.25 pad.@199,156.25 pad.@199,159 pad.@199,165.25 pad.@199,168.25 Q4.2 Q6.2 Q8.2 Q10.2 Q12.2 Q14.2 Q16.2 Q18.2 Q20.2 Q22.2 Q24.2 Q26.2 Q28.2 Q30.2 Q32.2 Q34.2 Q36.2 Q38.2 Q40.2 Q42.2 Q44.2 Q46.2 Q48.2 Q50.2 R134.2 R135.2 R138.1 R141.1 R144.1 R242.1 R244.1 R290.2 R292.1 R294.1 R298.1 R299.1 R313.2 R314.2 R315.2 R316.2 R317.2 R318.2 R319.2 R320.2 R321.2 R322.2 R323.2 R324.2 R325.2 R326.2 R327.2 R328.2 R329.2 R330.2 R331.2 R332.2 R333.2 R334.2 R335.2 R336.2 S1.5 S1.6 S1.7 S1.8 S2.3 S2.4 S2.5 | length 343
  TOP w0.2: IC16.6@169.4,140 168.5,140 168.3,140.2 pad.@168.3,140.55 168.747,140.5 IC16.5@169.4,140.5 ; pad.@171.15,140.5 IC16.4@172.1,140.5 ; pad.@171.25,146.05 171.25,145.5 IC18.4@172.1,145.5 ; pad.@177.9,140.5 IC17.4@178.85,140.5 ; pad.@179,145.95 179,145.5 IC15.4@179.85,145.5 ; pad.@184.65,140.5 IC14.4@185.6,140.5 ; pad.@186.75,145.95 186.75,145.5 IC13.4@187.6,145.5
  TOP w0.3: pad.@119.55,146.25 120.3,147 IC7.62@121.2,147 122.25,147 pad.@122.75,146.5 ; pad.@119.9,140.5 IC7.75@121.2,140.5 122.6,140.5 ; pad.@119.9,143.5 IC7.69@121.2,143.5 122.6,143.5 ; pad.@126.8,136.95 126.8,137.65 127,137.85 IC7.84@127,138.7 pad.@127,140.05 ; pad.@132.5,153 IC7.31@132.5,154.3 ; C37.2@135,137.25 IC7.100@135,138.7 ; pad.@135.5,150.5 IC7.21@136.8,150.5 138.3,150.5 C33.2@138.4,150.4 ; pad.@135.5,152.2 135.8,152.5 IC7.25@136.8,152.5 ; 149.3,133.15 159.5,133.15
  TOP w0.35: IC6.10@151.75,142.825 pad.@153.45,142.825 ; IC8.10@151.75,151.825 pad.@153.05,151.825
  TOP w0.4: pad.@171,150 IC21.2@172.1,150 R144.1@173.25,150 ; 173.25,149.25 R144.1@173.25,150 ; 174.2,150 R144.1@173.25,150 ; pad.@175.5,150 IC20.2@176.6,150 R141.1@177.75,150 178.65,150 ; pad.@180,150 IC19.2@181.1,150 R138.1@182.25,150 183.1,150 ; pad.@184.5,150 IC9.2@185.6,150 186.65,150
  TOP w0.5: IC10.5@84.932,79.245 pad.@86.35,79.245 86.605,79.5 R290.2@87.25,79.5 ; pad.@87.4,82.15 C61.2@87.4,83.05 ; 118,166.75 CN4.13@119.5,166.75 119.5,168.15 ; pad.@119.35,147.55 C41.2@119.35,148.4 ; C35.2@119.75,153.5 pad.@119.75,154.35 ; 121.5,168.15 CN4.11@121.5,166.75 CN4.9@123.5,166.75 ; 123.5,168.15 CN4.9@123.5,166.75 ; 125.5,168.15 CN4.7@125.5,166.75 ; pad.@127.15,155.75 C34.2@128,155.75 ; 127.5,168.15 CN4.5@127.5,166.75 ; v1(128,136.35) C36.2@128,137.25 ; 129.5,168.2 CN4.3@129.5,166.75 ; 131.5,168.15 CN4.1@131.5,166.75 ; 132.85,166.75 CN4.1@131.5,166.75 ; C37.2@135,137.25 pad.@135.85,137.25 ; C42.2@136.1,155.75 136.1,156.35 pad.@136.4,156.65 ; pad.@138.25,140.65 C32.2@138.25,141.5 ; v1(140.5,148.1) C46.2@140.5,149 ; C102.2@148.5,136.15 149.95,136.15 S2.5@150.3,136.5 ; C39.2@152.75,150 153.6,150 pad.@153.6,150.15 ; C44.2@152.75,159 153.6,159 pad.@153.6,159.25 ; pad.@155.65,150 C38.2@156.5,150 ; pad.@155.9,159 C43.2@156.75,159 ; 170.5,136.9 C94.2@170.5,137.75 170.5,139.85 pad.@171.15,140.5 ; 170.5,142 C95.2@170.5,142.75 170.5,145.3 pad.@171.25,146.05 ; C101.2@171,148 pad.@171,150 ; C136.2@171.35,154 pad.@172.2,154 ; pad.@173.15,142.6 C141.2@173.15,143.45 ; C99.2@175.5,148 pad.@175.5,150 ; C135.2@175.85,154.05 pad.@176.7,154.05 ; 177.25,136.9 C93.2@177.25,137.75 177.25,139.85 pad.@177.9,140.5 ; 178.25,141.95 C92.2@178.25,142.75 178.25,145.2 pad.@179,145.95 ; C97.2@180,148 pad.@180,150 ; C134.2@180.35,154 pad.@181.2,154 ; pad.@180.9,142.6 C140.2@180.9,143.45 ; C75.2@180.95,126.65 pad.@181.85,126.65 ; C133.2@183.5,153 pad.@183.5,153.9 ; 184,136.9 C91.2@184,137.75 184,139.85 pad.@184.65,140.5 ; R292.1@184.5,126.5 184.5,125.855 pad.@184.755,125.6 IC11.5@184.755,124.182 ; C45.2@184.5,148 pad.@184.5,150 ; 186,141.95 C90.2@186,142.75 186,145.2 pad.@186.75,145.95 ; pad.@188.65,142.6 C139.2@188.65,143.45 ; C89.2@196.6,160.1 pad.@196.6,161 ; R294.1@196.75,163.65 197.395,163.65 pad.@197.65,163.905 IC12.5@199.067,163.905 ; CN4.9@123.5,166.75 CN4.7@125.5,166.75 ; CN4.7@125.5,166.75 CN4.5@127.5,166.75 ; CN4.5@127.5,166.75 CN4.3@129.5,166.75 ; CN4.3@129.5,166.75 CN4.1@131.5,166.75
  TOP w0.6: pad.@90.85,141.8 pad.@90.85,145.6 ; pad.@98,137.5 IC5.2@98,138.7 ; C29.2@100.6,140.25 pad.@100.6,139.25 100.75,139.1 C30.2@100.75,138 ; pad.@107.5,137.5 IC4.2@107.5,138.7 ; S1.8@109.095,155.56 pad.@109.095,156.8 ; C28.2@110.15,140.25 pad.@110.15,139.2 110.25,139.1 C25.2@110.25,138 ; S1.7@110.365,155.56 pad.@110.365,156.8 ; S1.6@111.635,155.56 pad.@111.635,156.8 ; S1.5@112.905,155.56 pad.@112.905,156.8 ; pad.@117.05,147.7 C40.2@118.1,147.7 118.25,147.55 pad.@119.35,147.55 ; C31.2@118.5,154.35 pad.@119.75,154.35 ; IC22.2@144.575,151.05 v1(145.75,151.05) ; pad.@144.8,129.25 pad.@154.05,129.25 pad.@163.3,129.25 170.45,129.25 ; C102.2@148.5,136.15 pad.@148.5,137.2 ; pad.@148.5,138.75 S2.4@150.3,138.75 ; S2.3@158.7,138.75 pad.@160.15,138.75 ; R135.2@164.5,147.6 pad.@164.5,148.65 ; R134.2@166,147.6 pad.@166,148.65 ; CN3.39@166.685,167.075 pad.@166.685,168.4 ; CN3.37@167.955,167.075 pad.@167.955,168.4 ; CN3.35@169.225,167.075 pad.@169.225,168.4 ; CN3.33@170.495,167.075 pad.@170.495,168.4 ; CN3.31@171.765,167.075 pad.@171.765,168.4 ; CN3.29@173.035,167.075 pad.@173.035,168.4
  TOP w0.7: pad.@181.925,162.75 CN3.16@181.925,164.205 pad.@181.925,165.7 CN3.15@181.925,167.075 ; pad.@190.815,162.75 CN3.2@190.815,164.205 CN3.1@190.815,167.075 pad.@190.815,168.4
  TOP w0.8: 83.1,163.5 R299.1@83.1,164.5 ; 83.1,168.15 R298.1@83.1,167 ; 84.25,164.5 R299.1@83.1,164.5 ; 84.35,167 R298.1@83.1,167 ; R299.1@83.1,164.5 R298.1@83.1,167
  Mid-Layer 1 w0.2: 198.25,88.3 v1(199.2,88.3) ; 198.5,97.55 v1(199.2,97.55) ; 198.55,116.05 v1(199.2,116.05) ; 198.65,106.8 v1(199.2,106.8)
  Mid-Layer 1 w0.44: 120,134.5 v3(121,135.5) ; 120,136.5 v3(121,135.5) ; 122,134.5 v3(121,135.5) ; 122,136.5 v3(121,135.5)
  Mid-Layer 1 w0.5: v1(140.5,148.1) 140.5,147.1 140.85,146.75 146.45,146.75 146.75,147.05 146.75,150.85 146.55,151.05 v1(145.75,151.05)
  Mid-Layer 2 w0.2: 198.45,88.3 v1(199.2,88.3) ; 198.45,106.8 v1(199.2,106.8) ; 198.55,97.55 v1(199.2,97.55) ; 198.55,116.05 v1(199.2,116.05) ; v1(198.75,128.5) 198.75,129.2
  Mid-Layer 2 w0.44: 120,134.5 v3(121,135.5) ; 120,136.5 v3(121,135.5) ; 122,134.5 v3(121,135.5) ; 122,136.5 v3(121,135.5)
  Mid-Layer 3 w0.2: v1(128,136.35) 128,137.1 ; 198.5,97.55 v1(199.2,97.55) ; 198.5,106.8 v1(199.2,106.8) ; 198.5,116.05 v1(199.2,116.05) ; 198.6,88.3 v1(199.2,88.3)
  Mid-Layer 3 w0.44: 120,134.5 v3(121,135.5) ; 120,136.5 v3(121,135.5) ; 122,134.5 v3(121,135.5) ; 122,136.5 v3(121,135.5)
  Mid-Layer 4 w0.2: 198.35,88.3 v1(199.2,88.3) ; 198.45,106.8 v1(199.2,106.8) ; 198.45,116.05 v1(199.2,116.05) ; 198.55,97.55 v1(199.2,97.55)
  Mid-Layer 4 w0.44: 120,134.5 v3(121,135.5) ; 120,136.5 v3(121,135.5) ; 122,134.5 v3(121,135.5) ; 122,136.5 v3(121,135.5)
  BOTTOM w0.2: 156.9,147.55 157.05,147.7 157.05,148.6 157,148.65
  BOTTOM w0.5: pad.@86.5,95.5 R319.2@87.35,95.5 Q16.2@87.35,96.5 ; pad.@86.5,104.75 R318.2@87.35,104.75 Q14.2@87.35,105.75 ; pad.@86.5,114 R317.2@87.35,114 Q12.2@87.35,115 ; pad.@86.65,126.9 R316.2@87.5,126.9 Q10.2@87.5,127.9 ; pad.@86.65,136.15 R315.2@87.5,136.15 Q8.2@87.5,137.15 ; pad.@86.65,145.4 R314.2@87.5,145.4 Q6.2@87.5,146.4 ; pad.@86.65,154.65 R313.2@87.5,154.65 Q4.2@87.5,155.65 ; 87.35,85.3 R320.2@87.35,86.25 Q18.2@87.35,87.25 ; Q20.2@108.35,126.75 R321.2@109.35,126.75 pad.@109.35,125.9 ; Q22.2@117.6,126.75 R322.2@118.6,126.75 pad.@118.6,125.9 ; 118.05,166.75 CN4.13@119.5,166.75 119.5,168.25 ; 119.75,135.5 v3(121,135.5) ; 121,134.25 v3(121,135.5) ; 121,136.75 v3(121,135.5) ; 121.5,168.25 CN4.11@121.5,166.75 CN4.9@123.5,166.75 ; 122.25,135.5 v3(121,135.5) ; 123.5,168.25 CN4.9@123.5,166.75 ; 125.5,168.25 CN4.7@125.5,166.75 ; Q24.2@126.85,126.75 R323.2@127.85,126.75 pad.@127.85,125.9 ; 127.5,168.25 CN4.5@127.5,166.75 ; 129.5,168.25 CN4.3@129.5,166.75 ; 131.5,168.25 CN4.1@131.5,166.75 ; 133.1,166.75 CN4.1@131.5,166.75 ; Q26.2@136.1,126.75 R324.2@137.1,126.75 pad.@137.1,125.9 ; pad.@144.8,129.25 144.95,129.4 R325.2@145.7,129.4 Q28.2@146.7,129.4 ; pad.@153.6,147 R242.1@154.5,147 ; pad.@153.6,156 R244.1@154.5,156 ; pad.@154.05,129.25 154.2,129.4 R326.2@154.95,129.4 Q30.2@155.95,129.4 ; pad.@163.3,129.25 163.45,129.4 R327.2@164.2,129.4 Q32.2@165.2,129.4 ; pad.@172.55,129.25 172.7,129.4 R328.2@173.45,129.4 Q34.2@174.45,129.4 ; Q44.2@196.5,128.1 R333.2@196.5,129.1 pad.@196.5,130 ; Q46.2@196.5,137.35 R334.2@196.5,138.35 pad.@196.5,139.25 ; Q48.2@196.5,146.6 R335.2@196.5,147.6 pad.@196.5,148.5 ; Q50.2@196.5,155.85 R336.2@196.5,156.85 pad.@196.5,157.75 ; Q36.2@197.4,87.85 R329.2@198.4,87.85 198.75,87.85 v1(199.2,88.3) ; Q38.2@197.4,97.1 R330.2@198.4,97.1 198.75,97.1 v1(199.2,97.55) ; Q40.2@197.4,106.35 R331.2@198.4,106.35 198.75,106.35 v1(199.2,106.8) ; Q42.2@197.4,115.6 R332.2@198.4,115.6 198.75,115.6 v1(199.2,116.05) ; CN4.9@123.5,166.75 CN4.7@125.5,166.75 ; CN4.7@125.5,166.75 CN4.5@127.5,166.75 ; CN4.5@127.5,166.75 CN4.3@129.5,166.75 ; CN4.3@129.5,166.75 CN4.1@131.5,166.75
  BOTTOM w0.6: pad.@186.75,145.95 187.3,146.5 pad.@188.35,146.5
HVU_1_4: C54.2 C56.1 D19.3 D19.4 D25.5 pad.@51,129.65 pad.@51,130.85 pad.@51,132.05 pad.@51,133.25 pad.@51,134.45 pad.@51,135.65 pad.@51,136.85 pad.@51,138.05 pad.@51.1,85.45 pad.@51.1,86.65 pad.@51.1,87.85 pad.@51.1,89.05 pad.@51.1,90.25 pad.@51.1,91.45 pad.@51.1,92.65 pad.@51.1,93.85 pad.@52.2,129.65 pad.@52.2,130.85 pad.@52.2,132.05 pad.@52.2,133.25 pad.@52.2,134.45 pad.@52.2,135.65 pad.@52.2,136.85 pad.@52.2,138.05 pad.@52.3,85.45 pad.@52.3,86.65 pad.@52.3,87.85 pad.@52.3,89.05 pad.@52.3,90.25 pad.@52.3,91.45 pad.@52.3,92.65 pad.@52.3,93.85 pad.@53.4,129.65 pad.@53.4,130.85 pad.@53.4,132.05 pad.@53.4,133.25 pad.@53.4,134.45 pad.@53.4,135.65 pad.@53.4,136.85 pad.@53.4,138.05 pad.@53.5,85.45 pad.@53.5,86.65 pad.@53.5,87.85 pad.@53.5,89.05 pad.@53.5,90.25 pad.@53.5,91.45 pad.@53.5,92.65 pad.@53.5,93.85 pad.@54.6,129.65 pad.@54.6,130.85 pad.@54.6,132.05 pad.@54.6,133.25 pad.@54.6,134.45 pad.@54.6,135.65 pad.@54.6,136.85 pad.@54.6,138.05 pad.@54.7,85.45 pad.@54.7,86.65 pad.@54.7,87.85 pad.@54.7,89.05 pad.@54.7,90.25 pad.@54.7,91.45 pad.@54.7,92.65 pad.@54.7,93.85 pad.@55.8,129.65 pad.@55.8,130.85 pad.@55.8,132.05 pad.@55.8,133.25 pad.@55.8,134.45 pad.@55.8,135.65 pad.@55.8,136.85 pad.@55.8,138.05 pad.@55.9,85.45 pad.@55.9,86.65 pad.@55.9,87.85 pad.@55.9,89.05 pad.@55.9,90.25 pad.@55.9,91.45 pad.@55.9,92.65 pad.@55.9,93.85 R195.2 R196.1 | length 21.6
  Mid-Layer 2 w0.44: 25.5,104.25 C56.1@26.5,105.25 ; 25.5,106.25 C56.1@26.5,105.25 ; 27.5,104.25 C56.1@26.5,105.25 ; 27.5,106.25 C56.1@26.5,105.25 ; 33,121.25 C54.2@34,122.25 ; 33,123.25 C54.2@34,122.25 ; 35,121.25 C54.2@34,122.25 ; 35,123.25 C54.2@34,122.25
  BOTTOM w1.2: C56.1@26.5,105.25 28.65,107.4 R196.1@28.65,109.5 ; R195.2@31.85,126.5 31.85,124.4 C54.2@34,122.25
HVU_2_4: C49.2 C54.1 D17.3 D17.4 D23.5 pad.@51,140.4 pad.@51,141.6 pad.@51,142.8 pad.@51,144 pad.@51,145.2 pad.@51,146.4 pad.@51,147.6 pad.@51,148.8 pad.@51.1,96.2 pad.@51.1,97.4 pad.@51.1,98.6 pad.@51.1,99.8 pad.@51.1,101 pad.@51.1,102.2 pad.@51.1,103.4 pad.@51.1,104.6 pad.@52.2,140.4 pad.@52.2,141.6 pad.@52.2,142.8 pad.@52.2,144 pad.@52.2,145.2 pad.@52.2,146.4 pad.@52.2,147.6 pad.@52.2,148.8 pad.@52.3,96.2 pad.@52.3,97.4 pad.@52.3,98.6 pad.@52.3,99.8 pad.@52.3,101 pad.@52.3,102.2 pad.@52.3,103.4 pad.@52.3,104.6 pad.@53.4,140.4 pad.@53.4,141.6 pad.@53.4,142.8 pad.@53.4,144 pad.@53.4,145.2 pad.@53.4,146.4 pad.@53.4,147.6 pad.@53.4,148.8 pad.@53.5,96.2 pad.@53.5,97.4 pad.@53.5,98.6 pad.@53.5,99.8 pad.@53.5,101 pad.@53.5,102.2 pad.@53.5,103.4 pad.@53.5,104.6 pad.@54.6,140.4 pad.@54.6,141.6 pad.@54.6,142.8 pad.@54.6,144 pad.@54.6,145.2 pad.@54.6,146.4 pad.@54.6,147.6 pad.@54.6,148.8 pad.@54.7,96.2 pad.@54.7,97.4 pad.@54.7,98.6 pad.@54.7,99.8 pad.@54.7,101 pad.@54.7,102.2 pad.@54.7,103.4 pad.@54.7,104.6 pad.@55.8,140.4 pad.@55.8,141.6 pad.@55.8,142.8 pad.@55.8,144 pad.@55.8,145.2 pad.@55.8,146.4 pad.@55.8,147.6 pad.@55.8,148.8 pad.@55.9,96.2 pad.@55.9,97.4 pad.@55.9,98.6 pad.@55.9,99.8 pad.@55.9,101 pad.@55.9,102.2 pad.@55.9,103.4 pad.@55.9,104.6 R194.2 R195.1 | length 21.6
  Mid-Layer 1 w0.44: 25.5,121.25 C54.1@26.5,122.25 ; 25.5,123.25 C54.1@26.5,122.25 ; 27.5,121.25 C54.1@26.5,122.25 ; 27.5,123.25 C54.1@26.5,122.25 ; 33,138.25 C49.2@34,139.25 ; 33,140.25 C49.2@34,139.25 ; 35,138.25 C49.2@34,139.25 ; 35,140.25 C49.2@34,139.25
  BOTTOM w1.2: C54.1@26.5,122.25 28.65,124.4 R195.1@28.65,126.5 ; R194.2@31.85,143.5 31.85,141.4 C49.2@34,139.25
HVU_3_4: C48.2 C49.1 D15.3 D15.4 D21.5 pad.@48.6,151.25 pad.@48.6,152.45 pad.@48.6,153.65 pad.@48.6,154.85 pad.@48.6,156.05 pad.@48.6,157.25 pad.@49.8,151.25 pad.@49.8,152.45 pad.@49.8,153.65 pad.@49.8,154.85 pad.@49.8,156.05 pad.@49.8,157.25 pad.@51,151.25 pad.@51,152.45 pad.@51,153.65 pad.@51,154.85 pad.@51,156.05 pad.@51,157.25 pad.@51.1,106.95 pad.@51.1,108.15 pad.@51.1,109.35 pad.@51.1,110.55 pad.@51.1,111.75 pad.@51.1,112.95 pad.@51.1,114.15 pad.@51.1,115.35 pad.@52.2,151.25 pad.@52.2,152.45 pad.@52.2,153.65 pad.@52.2,154.85 pad.@52.2,156.05 pad.@52.2,157.25 pad.@52.3,106.95 pad.@52.3,108.15 pad.@52.3,109.35 pad.@52.3,110.55 pad.@52.3,111.75 pad.@52.3,112.95 pad.@52.3,114.15 pad.@52.3,115.35 pad.@53.4,151.25 pad.@53.4,152.45 pad.@53.4,153.65 pad.@53.4,154.85 pad.@53.4,156.05 pad.@53.4,157.25 pad.@53.5,106.95 pad.@53.5,108.15 pad.@53.5,109.35 pad.@53.5,110.55 pad.@53.5,111.75 pad.@53.5,112.95 pad.@53.5,114.15 pad.@53.5,115.35 pad.@54.6,151.25 pad.@54.6,152.45 pad.@54.6,153.65 pad.@54.6,154.85 pad.@54.6,156.05 pad.@54.6,157.25 pad.@54.7,106.95 pad.@54.7,108.15 pad.@54.7,109.35 pad.@54.7,110.55 pad.@54.7,111.75 pad.@54.7,112.95 pad.@54.7,114.15 pad.@54.7,115.35 pad.@55.8,151.25 pad.@55.8,152.45 pad.@55.8,153.65 pad.@55.8,154.85 pad.@55.8,156.05 pad.@55.8,157.25 pad.@55.9,106.95 pad.@55.9,108.15 pad.@55.9,109.35 pad.@55.9,110.55 pad.@55.9,111.75 pad.@55.9,112.95 pad.@55.9,114.15 pad.@55.9,115.35 R193.2 R194.1 | length 21.6
  Mid-Layer 3 w0.44: 25.5,138.25 C49.1@26.5,139.25 ; 25.5,140.25 C49.1@26.5,139.25 ; 27.5,138.25 C49.1@26.5,139.25 ; 27.5,140.25 C49.1@26.5,139.25 ; 39.75,154.5 C48.2@40.75,155.5 ; 39.75,156.5 C48.2@40.75,155.5 ; 41.75,154.5 C48.2@40.75,155.5 ; 41.75,156.5 C48.2@40.75,155.5
  BOTTOM w1.2: C49.1@26.5,139.25 28.65,141.4 R194.1@28.65,143.5 ; R193.2@38.6,151.25 R193.2@38.6,151.5 38.6,153.35 C48.2@40.75,155.5
HVV_1_4: C69.2 C71.1 D31.3 D31.4 D37.5 pad.@125.95,90.25 pad.@125.95,91.45 pad.@125.95,92.65 pad.@125.95,93.85 pad.@125.95,95.05 pad.@127.15,90.25 pad.@127.15,91.45 pad.@127.15,92.65 pad.@127.15,93.85 pad.@127.15,95.05 pad.@128.35,90.25 pad.@128.35,91.45 pad.@128.35,92.65 pad.@128.35,93.85 pad.@128.35,95.05 pad.@129.55,90.25 pad.@129.55,91.45 pad.@129.55,92.65 pad.@129.55,93.85 pad.@129.55,95.05 pad.@130.75,90.25 pad.@130.75,91.45 pad.@130.75,92.65 pad.@130.75,93.85 pad.@130.75,95.05 pad.@131.95,90.25 pad.@131.95,91.45 pad.@131.95,92.65 pad.@131.95,93.85 pad.@131.95,95.05 pad.@133.15,90.25 pad.@133.15,91.45 pad.@133.15,92.65 pad.@133.15,93.85 pad.@133.15,95.05 pad.@134.35,90.25 pad.@134.35,91.45 pad.@134.35,92.65 pad.@134.35,93.85 pad.@134.35,95.05 pad.@170.15,89.15 pad.@170.15,90.35 pad.@170.15,91.55 pad.@170.15,92.75 pad.@170.15,93.95 pad.@170.15,95.15 pad.@171.35,87.95 pad.@171.35,89.15 pad.@171.35,90.35 pad.@171.35,91.55 pad.@171.35,92.75 pad.@171.35,93.95 pad.@171.35,95.15 pad.@172.55,87.95 pad.@172.55,89.15 pad.@172.55,90.35 pad.@172.55,91.55 pad.@172.55,92.75 pad.@172.55,93.95 pad.@172.55,95.15 pad.@173.75,87.95 pad.@173.75,89.15 pad.@173.75,90.35 pad.@173.75,91.55 pad.@173.75,92.75 pad.@173.75,93.95 pad.@173.75,95.15 pad.@174.95,87.95 pad.@174.95,89.15 pad.@174.95,90.35 pad.@174.95,91.55 pad.@174.95,92.75 pad.@174.95,93.95 pad.@174.95,95.15 pad.@176.15,89.15 pad.@176.15,90.35 pad.@176.15,91.55 pad.@176.15,92.75 pad.@176.15,93.95 pad.@176.15,95.15 R201.2 R202.1 | length 17.3
  Mid-Layer 2 w0.44: 160.5,74.75 C69.2@161.5,73.75 ; 160.75,73 C69.2@161.5,73.75 ; 162.25,73 C69.2@161.5,73.75 ; 162.5,74.75 C69.2@161.5,73.75 ; 169.75,79.5 C71.1@170.75,78.5 171.75,79.5
  BOTTOM w1.3: R201.2@159.35,78 159.35,75.9 C69.2@161.5,73.75 ; C71.1@170.75,78.5 172.9,76.35 R202.1@172.9,75
HVV_2_4: C65.2 C69.1 D29.3 D29.4 D35.5 pad.@115.2,90.25 pad.@115.2,91.45 pad.@115.2,92.65 pad.@115.2,93.85 pad.@115.2,95.05 pad.@116.4,90.25 pad.@116.4,91.45 pad.@116.4,92.65 pad.@116.4,93.85 pad.@116.4,95.05 pad.@117.6,90.25 pad.@117.6,91.45 pad.@117.6,92.65 pad.@117.6,93.85 pad.@117.6,95.05 pad.@118.8,90.25 pad.@118.8,91.45 pad.@118.8,92.65 pad.@118.8,93.85 pad.@118.8,95.05 pad.@120,90.25 pad.@120,91.45 pad.@120,92.65 pad.@120,93.85 pad.@120,95.05 pad.@121.2,90.25 pad.@121.2,91.45 pad.@121.2,92.65 pad.@121.2,93.85 pad.@121.2,95.05 pad.@122.4,90.25 pad.@122.4,91.45 pad.@122.4,92.65 pad.@122.4,93.85 pad.@122.4,95.05 pad.@123.6,90.25 pad.@123.6,91.45 pad.@123.6,92.65 pad.@123.6,93.85 pad.@123.6,95.05 pad.@159.4,90.35 pad.@159.4,91.55 pad.@159.4,92.75 pad.@159.4,93.95 pad.@159.4,95.15 pad.@160.6,90.35 pad.@160.6,91.55 pad.@160.6,92.75 pad.@160.6,93.95 pad.@160.6,95.15 pad.@161.8,90.35 pad.@161.8,91.55 pad.@161.8,92.75 pad.@161.8,93.95 pad.@161.8,95.15 pad.@163,90.35 pad.@163,91.55 pad.@163,92.75 pad.@163,93.95 pad.@163,95.15 pad.@164.2,90.35 pad.@164.2,91.55 pad.@164.2,92.75 pad.@164.2,93.95 pad.@164.2,95.15 pad.@165.4,90.35 pad.@165.4,91.55 pad.@165.4,92.75 pad.@165.4,93.95 pad.@165.4,95.15 pad.@166.6,90.35 pad.@166.6,91.55 pad.@166.6,92.75 pad.@166.6,93.95 pad.@166.6,95.15 pad.@167.8,90.35 pad.@167.8,91.55 pad.@167.8,92.75 pad.@167.8,93.95 pad.@167.8,95.15 R200.2 R201.1 | length 21.6
  Mid-Layer 1 w0.44: 128.5,72.75 C65.2@129.5,73.75 ; 128.5,74.75 C65.2@129.5,73.75 ; 130.5,72.75 C65.2@129.5,73.75 ; 130.5,74.75 C65.2@129.5,73.75 ; 153,72.75 C69.1@154,73.75 ; 153,74.75 C69.1@154,73.75 ; 155,72.75 C69.1@154,73.75 ; 155,74.75 C69.1@154,73.75
  BOTTOM w1.3: R200.2@127.35,78 127.35,75.9 C65.2@129.5,73.75 ; C69.1@154,73.75 156.15,75.9 R201.1@156.15,78
HVV_3_4: C63.2 C65.1 D27.3 D27.4 D33.5 pad.@105.55,89.05 pad.@105.55,90.25 pad.@105.55,91.45 pad.@105.55,92.65 pad.@105.55,93.85 pad.@105.55,95.05 pad.@106.75,89.05 pad.@106.75,90.25 pad.@106.75,91.45 pad.@106.75,92.65 pad.@106.75,93.85 pad.@106.75,95.05 pad.@107.95,89.05 pad.@107.95,90.25 pad.@107.95,91.45 pad.@107.95,92.65 pad.@107.95,93.85 pad.@107.95,95.05 pad.@109.15,89.05 pad.@109.15,90.25 pad.@109.15,91.45 pad.@109.15,92.65 pad.@109.15,93.85 pad.@109.15,95.05 pad.@110.35,89.05 pad.@110.35,90.25 pad.@110.35,91.45 pad.@110.35,92.65 pad.@110.35,93.85 pad.@110.35,95.05 pad.@111.55,89.05 pad.@111.55,90.25 pad.@111.55,91.45 pad.@111.55,92.65 pad.@111.55,93.85 pad.@111.55,95.05 pad.@112.75,89.05 pad.@112.75,90.25 pad.@112.75,91.45 pad.@112.75,92.65 pad.@112.75,93.85 pad.@112.75,95.05 pad.@148.65,90.35 pad.@148.65,91.55 pad.@148.65,92.75 pad.@148.65,93.95 pad.@148.65,95.15 pad.@149.85,90.35 pad.@149.85,91.55 pad.@149.85,92.75 pad.@149.85,93.95 pad.@149.85,95.15 pad.@151.05,90.35 pad.@151.05,91.55 pad.@151.05,92.75 pad.@151.05,93.95 pad.@151.05,95.15 pad.@152.25,90.35 pad.@152.25,91.55 pad.@152.25,92.75 pad.@152.25,93.95 pad.@152.25,95.15 pad.@153.45,90.35 pad.@153.45,91.55 pad.@153.45,92.75 pad.@153.45,93.95 pad.@153.45,95.15 pad.@154.65,90.35 pad.@154.65,91.55 pad.@154.65,92.75 pad.@154.65,93.95 pad.@154.65,95.15 pad.@155.85,90.35 pad.@155.85,91.55 pad.@155.85,92.75 pad.@155.85,93.95 pad.@155.85,95.15 pad.@157.05,90.35 pad.@157.05,91.55 pad.@157.05,92.75 pad.@157.05,93.95 pad.@157.05,95.15 R199.2 R200.1 | length 21.6
  Mid-Layer 3 w0.44: 111.5,72.75 C63.2@112.5,73.75 ; 111.5,74.75 C63.2@112.5,73.75 ; 113.5,72.75 C63.2@112.5,73.75 ; 113.5,74.75 C63.2@112.5,73.75 ; 121,72.75 C65.1@122,73.75 ; 121,74.75 C65.1@122,73.75 ; 123,72.75 C65.1@122,73.75 ; 123,74.75 C65.1@122,73.75
  BOTTOM w1.3: R199.2@110.35,78 110.35,75.9 C63.2@112.5,73.75 ; C65.1@122,73.75 124.15,75.9 R200.1@124.15,78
